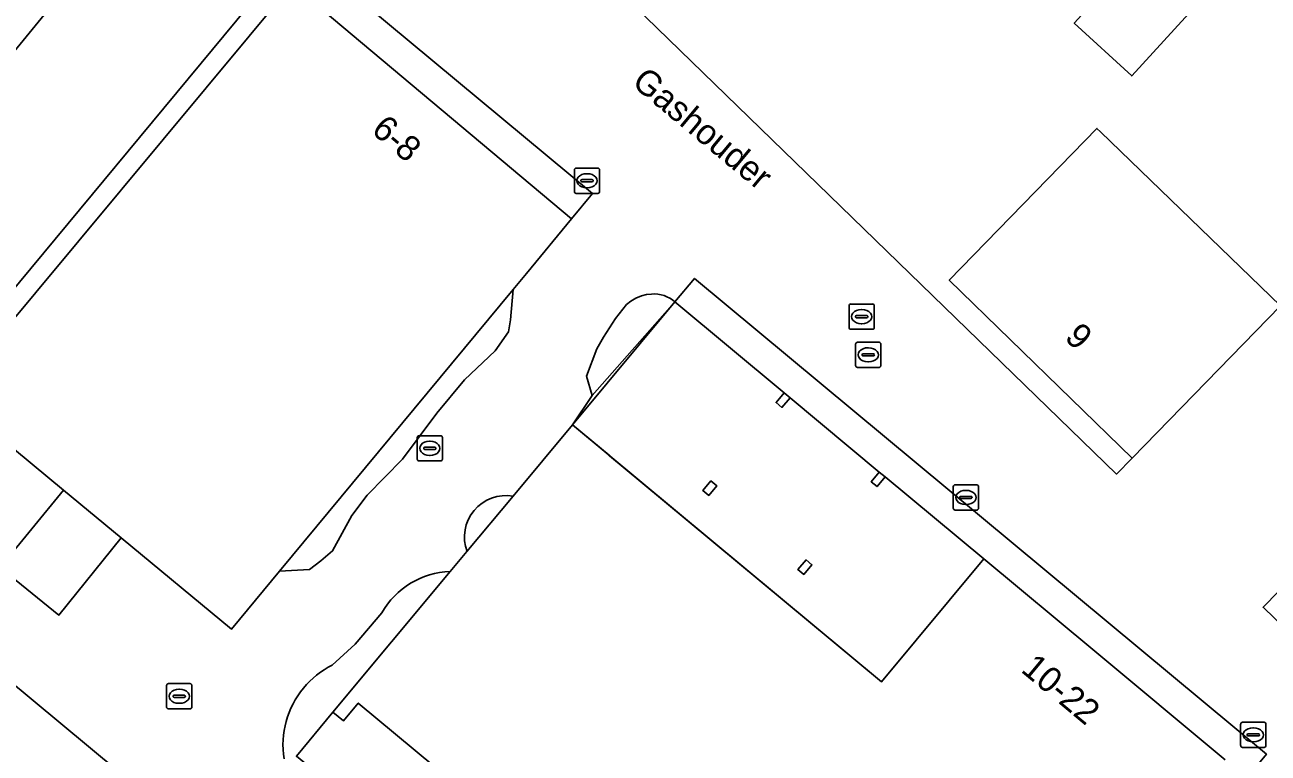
# Model space of a CAD drawing. Extents: x 161772 to 163126, y 383092 to 383917.
# Drawn here: x 162022.82 to 162072.09, y 383312.33 to 383341.19 of the extents above; entities that cross this region are included whole.
import ezdxf

# ---------------------------------------------------------------- set-up
doc = ezdxf.new("R2010")
doc.units = 0
for name, color, linetype in [('IMGEO_Erf', 7, 'Continuous'), ('IMGEO_Groenvoorziening', 7, 'Continuous'), ('IMGEO_Kolk', 7, 'Continuous'), ('IMGEO_Openbare_ruimte_label', 7, 'Continuous'), ('IMGEO_Pand', 7, 'Continuous'), ('IMGEO_Pand_nummerreeks', 7, 'Continuous'), ('IMGEO_Pand_overbouw', 7, 'Continuous'), ('IMGEO_Rijbaan_lokaal_open', 7, 'Continuous'), ('IMGEO_Rioolput', 7, 'Continuous'), ('IMGEO_Voetpad_open', 7, 'Continuous')]:
    doc.layers.add(name, color=color, linetype=linetype)

msp = doc.modelspace()

# ---------------------------------------------------------------- linework, layer by layer
at = {"layer": 'IMGEO_Erf'}
for points in [[(162085.05, 383335.095), (162085.636, 383334.487), (162109.459, 383358.96), (162108.772, 383359.637), (162097.704, 383370.546), (162075.222, 383392.703), (162064.395, 383381.925), (162038.775, 383357.03), (162035.617, 383357.251), (162035.13, 383353.454), (162066.087, 383323.385), (162066.709, 383324.02), (162059.456, 383331.069), (162065.31, 383337.087), (162065.453, 383336.949), (162072.586, 383330.051), (162076.509, 383326.257)], [(162075.322, 383348.619), (162071.07, 383343.965), (162066.692, 383339.172), (162064.408, 383341.259), (162066.693, 383343.76), (162064.816, 383345.474), (162067.017, 383347.884), (162068.953, 383350.003), (162070.79, 383348.325), (162072.998, 383350.742)], [(162033.597, 383344.262), (162019.25, 383326.968), (162019.834, 383326.482), (162033.413, 383342.802), (162044.491, 383333.503), (162045.324, 383334.504)], [(162052.827, 383326.029), (162052.596, 383326.221), (162052.916, 383326.605), (162053.147, 383326.413)], [(162049.694, 383322.734), (162050.014, 383323.119), (162050.245, 383322.927), (162049.925, 383322.542)], [(162056.595, 383322.893), (162056.364, 383323.085), (162056.684, 383323.469), (162056.914, 383323.277)], [(162026.638, 383320.859), (162024.353, 383322.748), (162021.848, 383319.686), (162024.174, 383317.796)], [(162053.693, 383319.407), (162053.462, 383319.598), (162053.782, 383319.983), (162054.013, 383319.791)]]:
    msp.add_lwpolyline(points, close=True, dxfattribs=at)
for points in [[(162009.958, 383330.454), (162012.665, 383328.248), (162026.145, 383344.722), (162027.077, 383344.535), (162029.829, 383357.939)], [(162072.028, 383312.283), (162049.364, 383331.142), (162048.587, 383330.208), (162045.306, 383326.504), (162044.527, 383325.337), (162045.975, 383324.132), (162045.995, 383324.116), (162047.241, 383323.078), (162056.77, 383315.147), (162060.827, 383320.021), (162065.145, 383316.427), (162070.392, 383312.06)], [(162042.035, 383309.324), (162036.038, 383314.311), (162035.447, 383313.601), (162035.032, 383313.946), (162033.589, 383312.199)]]:
    msp.add_lwpolyline(points, dxfattribs=at)
at = {"layer": 'IMGEO_Groenvoorziening'}
msp.add_lwpolyline([(162037.784, 383323.976), (162039.15, 383325.806), (162040.242, 383327.129), (162041.464, 383328.268), (162041.991, 383329.019), (162042.065, 383329.499), (162042.175, 383330.708), (162032.919, 383319.537), (162034.107, 383319.606), (162034.547, 383319.954), (162035.018, 383320.343), (162035.787, 383321.748), (162036.394, 383322.553)], close=True, dxfattribs=at)
for points in [[(162047.659, 383330.523), (162047.456, 383330.501), (162047.257, 383330.451), (162047.043, 383330.365), (162046.834, 383330.24), (162046.673, 383330.108), (162046.228, 383329.558), (162045.752, 383328.815), (162045.489, 383328.347), (162045.087, 383327.262), (162045.306, 383326.504), (162048.587, 383330.208)], [(162040.346, 383320.322), (162042.171, 383322.511)], [(162034.575, 383310.172), (162035.375, 383309.727), (162036.79, 383308.876), (162038.794, 383307.136), (162040.846, 383305.465), (162041.519, 383305.093), (162042.479, 383304.929), (162033.589, 383312.199), (162035.032, 383313.946), (162039.678, 383319.519)], [(162036.968, 383317.883), (162035.912, 383316.644), (162035.005, 383315.814)]]:
    msp.add_lwpolyline(points, dxfattribs=at)
for centre, radius, start, end in [((162047.754, 383329.278), 1.249, 48.1445, 94.357), ((162041.887, 383320.892), 1.643, 80.0601, 200.303), ((162039.769, 383316.306), 3.214, 91.6196, 150.6183), ((162036.618, 383312.63), 3.57, 116.8601, 140.4595), ((162036.612, 383312.639), 3.559, 140.5165, 188.7139)]:
    msp.add_arc(centre, radius, start, end, dxfattribs=at)
at = {"layer": 'IMGEO_Kolk'}
for p, q in [((162044.602, 383334.588), (162044.602, 383335.44)), ((162044.677, 383335.514), (162045.529, 383335.514)), ((162045.603, 383335.44), (162045.603, 383334.588)), ((162044.861, 383335.008), (162044.861, 383335.02)), ((162045.299, 383334.971), (162044.901, 383334.971)), ((162044.904, 383335.057), (162045.302, 383335.057)), ((162045.09, 383335.294), (162045.115, 383335.294)), ((162045.345, 383335.02), (162045.345, 383335.008)), ((162045.529, 383334.514), (162044.677, 383334.514)), ((162045.113, 383334.734), (162045.088, 383334.734)), ((162038.372, 383323.98), (162038.372, 383324.832)), ((162038.447, 383324.906), (162039.299, 383324.906)), ((162038.86, 383324.686), (162038.885, 383324.686)), ((162039.373, 383324.832), (162039.373, 383323.98)), ((162038.631, 383324.4), (162038.631, 383324.412)), ((162039.069, 383324.363), (162038.671, 383324.363)), ((162038.674, 383324.449), (162039.072, 383324.449)), ((162038.883, 383324.126), (162038.858, 383324.126)), ((162039.115, 383324.412), (162039.115, 383324.4)), ((162039.299, 383323.906), (162038.447, 383323.906)), ((162059.617, 383322.035), (162059.617, 383322.887)), ((162059.692, 383322.961), (162060.544, 383322.961)), ((162060.105, 383322.741), (162060.13, 383322.741)), ((162060.618, 383322.887), (162060.618, 383322.035)), ((162059.876, 383322.455), (162059.876, 383322.467)), ((162060.314, 383322.418), (162059.916, 383322.418)), ((162059.919, 383322.504), (162060.317, 383322.504)), ((162060.128, 383322.181), (162060.103, 383322.181)), ((162060.36, 383322.467), (162060.36, 383322.455)), ((162060.544, 383321.961), (162059.692, 383321.961)), ((162028.441, 383314.154), (162028.441, 383315.006)), ((162028.516, 383315.08), (162029.368, 383315.08)), ((162028.929, 383314.86), (162028.954, 383314.86)), ((162029.442, 383315.006), (162029.442, 383314.154)), ((162028.7, 383314.574), (162028.7, 383314.586)), ((162029.138, 383314.537), (162028.74, 383314.537)), ((162028.743, 383314.623), (162029.141, 383314.623)), ((162028.952, 383314.3), (162028.927, 383314.3)), ((162029.184, 383314.586), (162029.184, 383314.574)), ((162029.368, 383314.08), (162028.516, 383314.08)), ((162071.006, 383312.625), (162071.006, 383313.477)), ((162071.081, 383313.551), (162071.933, 383313.551)), ((162071.494, 383313.331), (162071.519, 383313.331)), ((162072.007, 383313.477), (162072.007, 383312.625)), ((162071.265, 383313.045), (162071.265, 383313.057)), ((162071.703, 383313.008), (162071.305, 383313.008)), ((162071.308, 383313.094), (162071.706, 383313.094)), ((162071.517, 383312.771), (162071.492, 383312.771)), ((162071.749, 383313.057), (162071.749, 383313.045)), ((162071.933, 383312.551), (162071.081, 383312.551))]:
    msp.add_line(p, q, dxfattribs=at)
for points in [[(162044.602, 383334.588), (162044.602, 383335.44)], [(162044.677, 383335.514), (162045.529, 383335.514)], [(162045.603, 383335.44), (162045.603, 383334.588)], [(162045.529, 383334.514), (162044.677, 383334.514)], [(162038.372, 383323.98), (162038.372, 383324.832)], [(162038.447, 383324.906), (162039.299, 383324.906)], [(162039.373, 383324.832), (162039.373, 383323.98)], [(162039.299, 383323.906), (162038.447, 383323.906)], [(162059.617, 383322.035), (162059.617, 383322.887)], [(162059.692, 383322.961), (162060.544, 383322.961)], [(162060.618, 383322.887), (162060.618, 383322.035)], [(162060.544, 383321.961), (162059.692, 383321.961)], [(162028.441, 383314.154), (162028.441, 383315.006)], [(162028.516, 383315.08), (162029.368, 383315.08)], [(162029.442, 383315.006), (162029.442, 383314.154)], [(162029.368, 383314.08), (162028.516, 383314.08)], [(162071.006, 383312.625), (162071.006, 383313.477)], [(162071.081, 383313.551), (162071.933, 383313.551)], [(162072.007, 383313.477), (162072.007, 383312.625)], [(162071.933, 383312.551), (162071.081, 383312.551)]]:
    msp.add_lwpolyline(points, dxfattribs=at)
for centre, radius, start, end in [((162044.679, 383335.438), 0.0765, 91.552, 178.448), ((162044.679, 383335.438), 0.0765, 91.552, 178.448), ((162045.527, 383335.438), 0.0765, 1.552, 88.448), ((162045.527, 383335.438), 0.0765, 1.552, 88.448), ((162044.901, 383335.017), 0.0403, 85.8775, 175.7526), ((162044.898, 383335.007), 0.0366, 178.938, 274.7102), ((162045.302, 383335.014), 0.043, 264.8664, 352.4533), ((162045.306, 383335.019), 0.0386, 1.7309, 96.639), ((162044.679, 383334.59), 0.0765, 181.552, 268.448), ((162044.679, 383334.59), 0.0765, 181.552, 268.448), ((162045.527, 383334.59), 0.0765, 271.552, 358.448), ((162045.527, 383334.59), 0.0765, 271.552, 358.448), ((162038.449, 383324.83), 0.0765, 91.552, 178.448), ((162038.449, 383324.83), 0.0765, 91.552, 178.448), ((162039.297, 383324.83), 0.0765, 1.552, 88.448), ((162039.297, 383324.83), 0.0765, 1.552, 88.448), ((162038.671, 383324.409), 0.0403, 85.8775, 175.7526), ((162038.668, 383324.399), 0.0366, 178.938, 274.7102), ((162039.072, 383324.406), 0.043, 264.8664, 352.4533), ((162039.076, 383324.411), 0.0386, 1.7309, 96.639), ((162038.449, 383323.982), 0.0765, 181.552, 268.448), ((162038.449, 383323.982), 0.0765, 181.552, 268.448), ((162039.297, 383323.982), 0.0765, 271.552, 358.448), ((162039.297, 383323.982), 0.0765, 271.552, 358.448), ((162059.694, 383322.885), 0.0765, 91.552, 178.448), ((162059.694, 383322.885), 0.0765, 91.552, 178.448), ((162060.542, 383322.885), 0.0765, 1.552, 88.448), ((162060.542, 383322.885), 0.0765, 1.552, 88.448), ((162059.916, 383322.464), 0.0403, 85.8775, 175.7526), ((162059.913, 383322.454), 0.0366, 178.938, 274.7102), ((162060.317, 383322.461), 0.043, 264.8664, 352.4533), ((162060.321, 383322.466), 0.0386, 1.7309, 96.639), ((162059.694, 383322.037), 0.0765, 181.552, 268.448), ((162059.694, 383322.037), 0.0765, 181.552, 268.448), ((162060.542, 383322.037), 0.0765, 271.552, 358.448), ((162060.542, 383322.037), 0.0765, 271.552, 358.448), ((162028.518, 383315.004), 0.0765, 91.552, 178.448), ((162028.518, 383315.004), 0.0765, 91.552, 178.448), ((162029.366, 383315.004), 0.0765, 1.552, 88.448), ((162029.366, 383315.004), 0.0765, 1.552, 88.448), ((162028.74, 383314.583), 0.0403, 85.8775, 175.7526), ((162028.737, 383314.573), 0.0366, 178.938, 274.7102), ((162029.141, 383314.58), 0.043, 264.8664, 352.4533), ((162029.145, 383314.585), 0.0386, 1.7309, 96.639), ((162028.518, 383314.156), 0.0765, 181.552, 268.448), ((162028.518, 383314.156), 0.0765, 181.552, 268.448), ((162029.366, 383314.156), 0.0765, 271.552, 358.448), ((162029.366, 383314.156), 0.0765, 271.552, 358.448), ((162071.083, 383313.475), 0.0765, 91.552, 178.448), ((162071.083, 383313.475), 0.0765, 91.552, 178.448), ((162071.931, 383313.475), 0.0765, 1.552, 88.448), ((162071.931, 383313.475), 0.0765, 1.552, 88.448), ((162071.305, 383313.054), 0.0403, 85.8775, 175.7526), ((162071.302, 383313.044), 0.0366, 178.938, 274.7102), ((162071.706, 383313.051), 0.043, 264.8664, 352.4533), ((162071.71, 383313.056), 0.0386, 1.7309, 96.639), ((162071.083, 383312.627), 0.0765, 181.552, 268.448), ((162071.083, 383312.627), 0.0765, 181.552, 268.448), ((162071.931, 383312.627), 0.0765, 271.552, 358.448), ((162071.931, 383312.627), 0.0765, 271.552, 358.448)]:
    msp.add_arc(centre, radius, start, end, dxfattribs=at)
for centre, major_axis, ratio, start_param, end_param in [((162045.089, 383335.014), (-0.387, 0.002), 0.722429, 4.712389, 7.853982), ((162045.114, 383335.014), (-0.39, 0.002), 0.717154, 1.570796, 4.712389), ((162038.859, 383324.406), (-0.387, 0.002), 0.722429, 4.712389, 7.853982), ((162038.884, 383324.406), (-0.39, 0.002), 0.717154, 1.570796, 4.712389), ((162060.104, 383322.461), (-0.387, 0.002), 0.722429, 4.712389, 7.853982), ((162060.129, 383322.461), (-0.39, 0.002), 0.717154, 1.570796, 4.712389), ((162028.928, 383314.58), (-0.387, 0.002), 0.722429, 4.712389, 7.853982), ((162028.953, 383314.58), (-0.39, 0.002), 0.717154, 1.570796, 4.712389), ((162071.493, 383313.051), (-0.387, 0.002), 0.722429, 4.712389, 7.853982), ((162071.518, 383313.051), (-0.39, 0.002), 0.717154, 1.570796, 4.712389)]:
    msp.add_ellipse(centre, major_axis=major_axis, ratio=ratio, start_param=start_param, end_param=end_param, dxfattribs=at)
at = {"layer": 'IMGEO_Pand'}
for points in [[(162071.07, 383343.965), (162067.017, 383347.884), (162064.816, 383345.474), (162066.693, 383343.76), (162064.408, 383341.259), (162066.692, 383339.172)], [(162042.175, 383330.708), (162042.699, 383331.34), (162044.491, 383333.503), (162033.413, 383342.802), (162019.834, 383326.482), (162024.353, 383322.748), (162026.638, 383320.859), (162031.017, 383317.241), (162032.919, 383319.537)], [(162065.31, 383337.087), (162059.456, 383331.069), (162066.709, 383324.02), (162072.586, 383330.051), (162065.453, 383336.949)], [(162053.147, 383326.413), (162052.916, 383326.605), (162052.596, 383326.221), (162052.827, 383326.029)], [(162050.245, 383322.927), (162050.014, 383323.119), (162049.694, 383322.734), (162049.925, 383322.542)], [(162056.914, 383323.277), (162056.684, 383323.469), (162056.364, 383323.085), (162056.595, 383322.893)], [(162054.013, 383319.791), (162053.782, 383319.983), (162053.462, 383319.598), (162053.693, 383319.407)], [(162026.521, 383311.615), (162017.506, 383319.099), (161999.317, 383297.187), (162008.327, 383289.709)]]:
    msp.add_lwpolyline(points, close=True, dxfattribs=at)
msp.add_lwpolyline([(162070.392, 383312.06), (162065.145, 383316.427), (162060.827, 383320.021), (162056.77, 383315.147), (162047.241, 383323.078), (162045.995, 383324.116), (162045.975, 383324.132), (162044.527, 383325.337), (162042.171, 383322.511), (162040.346, 383320.322), (162039.678, 383319.519), (162035.032, 383313.946), (162035.447, 383313.601), (162036.038, 383314.311), (162042.035, 383309.324)], dxfattribs=at)
at = {"layer": 'IMGEO_Pand_overbouw'}
msp.add_lwpolyline([(162056.684, 383323.469), (162053.147, 383326.413), (162052.916, 383326.605), (162048.587, 383330.208), (162044.527, 383325.337), (162056.77, 383315.147), (162060.827, 383320.021), (162056.914, 383323.277)], close=True, dxfattribs=at)
at = {"layer": 'IMGEO_Rijbaan_lokaal_open'}
for points in [[(162109.459, 383358.96), (162085.636, 383334.487), (162085.05, 383335.095), (162076.509, 383326.257), (162072.586, 383330.051), (162066.709, 383324.02), (162066.087, 383323.385), (162035.13, 383353.454)], [(162026.145, 383344.722), (162012.665, 383328.248), (162010.273, 383325.262), (162012.491, 383323.441), (162013.295, 383322.786), (161999.43, 383305.781), (161998.722, 383306.358), (161996.242, 383303.323)], [(162048.587, 383330.208), (162049.364, 383331.142), (162072.028, 383312.283), (162056.483, 383293.468), (162055.615, 383294.185), (162055.275, 383293.878), (162054.805, 383293.179), (162054.336, 383292.297)], [(162042.171, 383322.511), (162044.527, 383325.337), (162045.306, 383326.504), (162045.087, 383327.262), (162045.489, 383328.347), (162045.752, 383328.815), (162046.228, 383329.558), (162046.673, 383330.108), (162046.834, 383330.24), (162047.043, 383330.365), (162047.257, 383330.451), (162047.456, 383330.501), (162047.659, 383330.523)], [(162039.678, 383319.519), (162040.346, 383320.322)], [(162035.005, 383315.814), (162035.912, 383316.644), (162036.968, 383317.883)]]:
    msp.add_lwpolyline(points, dxfattribs=at)
for points in [[(162021.848, 383319.686), (162024.353, 383322.748), (162019.834, 383326.482), (162019.25, 383326.968), (162033.597, 383344.262), (162045.324, 383334.504), (162044.491, 383333.503), (162042.699, 383331.34), (162042.175, 383330.708), (162042.065, 383329.499), (162041.991, 383329.019), (162041.464, 383328.268), (162040.242, 383327.129), (162039.15, 383325.806), (162037.784, 383323.976), (162036.394, 383322.553), (162035.787, 383321.748), (162035.018, 383320.343), (162034.547, 383319.954), (162034.107, 383319.606), (162032.919, 383319.537), (162031.017, 383317.241), (162026.638, 383320.859), (162024.174, 383317.796)], [(162082.872, 383329.333), (162094.093, 383318.339), (162083.161, 383307.175), (162071.894, 383318.107)], [(162008.327, 383289.709), (161999.317, 383297.187), (161998.671, 383297.723), (162016.845, 383319.622), (162017.506, 383319.099), (162026.521, 383311.615)]]:
    msp.add_lwpolyline(points, close=True, dxfattribs=at)
for centre, radius, start, end in [((162047.754, 383329.278), 1.249, 48.1445, 94.357), ((162041.887, 383320.892), 1.643, 80.0601, 200.303), ((162039.769, 383316.306), 3.214, 91.6196, 150.6183), ((162036.618, 383312.63), 3.57, 116.8601, 140.4595), ((162036.612, 383312.639), 3.559, 140.5165, 188.7139)]:
    msp.add_arc(centre, radius, start, end, dxfattribs=at)
at = {"layer": 'IMGEO_Rioolput'}
for p, q in [((162055.486, 383329.202), (162055.486, 383330.054)), ((162055.561, 383330.128), (162056.413, 383330.128)), ((162056.487, 383330.054), (162056.487, 383329.202)), ((162055.745, 383329.622), (162055.745, 383329.634)), ((162056.183, 383329.585), (162055.785, 383329.585)), ((162055.788, 383329.671), (162056.186, 383329.671)), ((162055.974, 383329.908), (162055.999, 383329.908)), ((162056.229, 383329.634), (162056.229, 383329.622)), ((162056.413, 383329.128), (162055.561, 383329.128)), ((162055.997, 383329.348), (162055.972, 383329.348)), ((162055.747, 383327.688), (162055.747, 383328.54)), ((162055.822, 383328.614), (162056.674, 383328.614)), ((162056.748, 383328.54), (162056.748, 383327.688)), ((162056.006, 383328.108), (162056.006, 383328.12)), ((162056.444, 383328.071), (162056.046, 383328.071)), ((162056.049, 383328.157), (162056.447, 383328.157)), ((162056.235, 383328.394), (162056.26, 383328.394)), ((162056.49, 383328.12), (162056.49, 383328.108)), ((162056.674, 383327.614), (162055.822, 383327.614)), ((162056.258, 383327.834), (162056.233, 383327.834))]:
    msp.add_line(p, q, dxfattribs=at)
for points in [[(162055.486, 383329.202), (162055.486, 383330.054)], [(162055.561, 383330.128), (162056.413, 383330.128)], [(162056.487, 383330.054), (162056.487, 383329.202)], [(162056.413, 383329.128), (162055.561, 383329.128)], [(162055.747, 383327.688), (162055.747, 383328.54)], [(162055.822, 383328.614), (162056.674, 383328.614)], [(162056.748, 383328.54), (162056.748, 383327.688)], [(162056.674, 383327.614), (162055.822, 383327.614)]]:
    msp.add_lwpolyline(points, dxfattribs=at)
for centre, radius, start, end in [((162055.563, 383330.052), 0.0765, 91.552, 178.448), ((162055.563, 383330.052), 0.0765, 91.552, 178.448), ((162056.411, 383330.052), 0.0765, 1.552, 88.448), ((162056.411, 383330.052), 0.0765, 1.552, 88.448), ((162055.785, 383329.631), 0.0403, 85.8775, 175.7526), ((162055.782, 383329.621), 0.0366, 178.938, 274.7102), ((162056.186, 383329.628), 0.043, 264.8664, 352.4533), ((162056.19, 383329.633), 0.0386, 1.7309, 96.639), ((162055.563, 383329.204), 0.0765, 181.552, 268.448), ((162055.563, 383329.204), 0.0765, 181.552, 268.448), ((162056.411, 383329.204), 0.0765, 271.552, 358.448), ((162056.411, 383329.204), 0.0765, 271.552, 358.448), ((162055.824, 383328.538), 0.0765, 91.552, 178.448), ((162055.824, 383328.538), 0.0765, 91.552, 178.448), ((162056.672, 383328.538), 0.0765, 1.552, 88.448), ((162056.672, 383328.538), 0.0765, 1.552, 88.448), ((162056.046, 383328.117), 0.0403, 85.8775, 175.7526), ((162056.043, 383328.107), 0.0366, 178.938, 274.7102), ((162056.447, 383328.114), 0.043, 264.8664, 352.4533), ((162056.451, 383328.119), 0.0386, 1.7309, 96.639), ((162055.824, 383327.69), 0.0765, 181.552, 268.448), ((162055.824, 383327.69), 0.0765, 181.552, 268.448), ((162056.672, 383327.69), 0.0765, 271.552, 358.448), ((162056.672, 383327.69), 0.0765, 271.552, 358.448)]:
    msp.add_arc(centre, radius, start, end, dxfattribs=at)
for centre, major_axis, ratio, start_param, end_param in [((162055.973, 383329.628), (-0.387, 0.002), 0.722429, 4.712389, 7.853982), ((162055.998, 383329.628), (-0.39, 0.002), 0.717154, 1.570796, 4.712389), ((162056.234, 383328.114), (-0.387, 0.002), 0.722429, 4.712389, 7.853982), ((162056.259, 383328.114), (-0.39, 0.002), 0.717154, 1.570796, 4.712389)]:
    msp.add_ellipse(centre, major_axis=major_axis, ratio=ratio, start_param=start_param, end_param=end_param, dxfattribs=at)
at = {"layer": 'IMGEO_Voetpad_open'}
msp.add_lwpolyline([(162082.872, 383329.333), (162071.894, 383318.107), (162083.161, 383307.175), (162094.093, 383318.339)], close=True, dxfattribs=at)

# ---------------------------------------------------------------- texts
at = {"layer": 'IMGEO_Openbare_ruimte_label'}
msp.add_text('Gashouder', height=1, rotation=320.1944, dxfattribs=at).set_placement((162046.831, 383338.83))
at = {"layer": 'IMGEO_Pand_nummerreeks'}
for s, rotation, p in [('6-8', 319.7898, (162036.511, 383336.943)), ('9', 315.8192, (162063.988, 383328.756)), ('10-22', 320.231, (162062.258, 383315.577))]:
    msp.add_text(s, height=1, rotation=rotation, dxfattribs=at).set_placement(p)

doc.saveas('drawing.dxf')
